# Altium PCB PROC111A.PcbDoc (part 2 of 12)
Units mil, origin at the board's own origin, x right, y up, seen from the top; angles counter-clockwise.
Board outline 7700 x 2300 mil, 6 copper layers (Top Layer, GND 1, SIG 1, SIG 2, GND 2, Bottom Layer), stack 61.062 mil thick; 841 components, 632 nets, 2914 pads, 1627 vias.
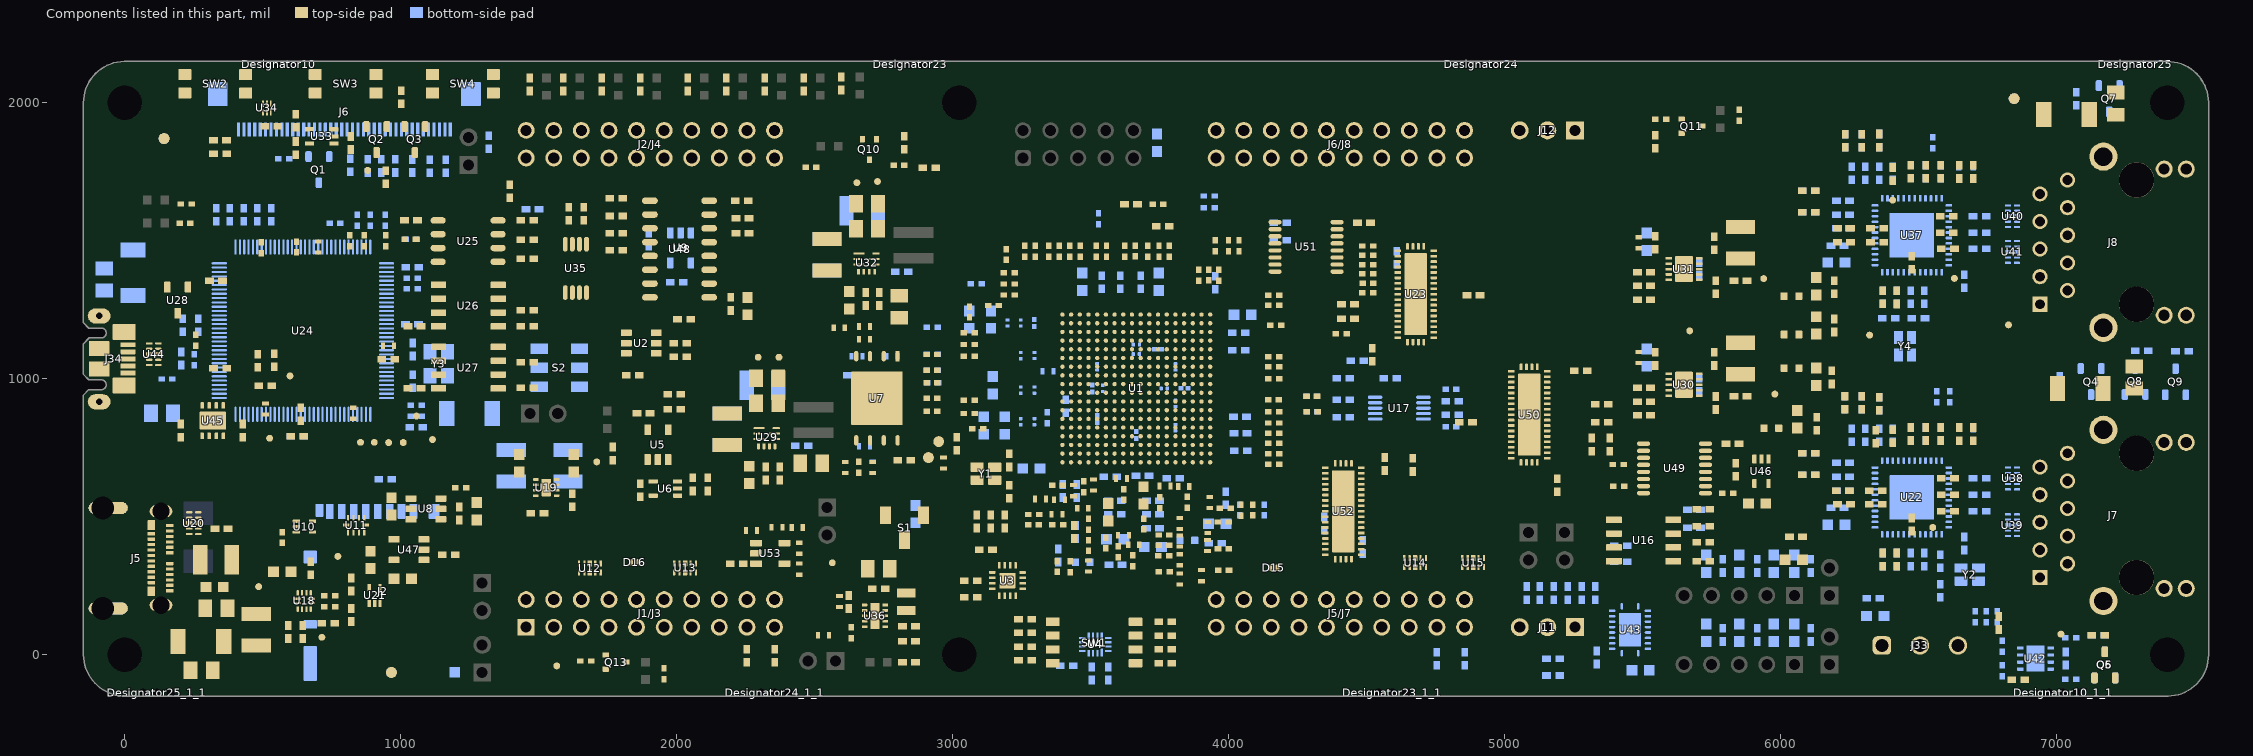
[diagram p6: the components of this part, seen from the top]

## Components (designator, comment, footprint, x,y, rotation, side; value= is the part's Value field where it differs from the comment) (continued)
Q3 "IRLML6401TRPBF" SOT-23 1051.12,1867.02 r270 top value=-12V
Q4 "BSS123" SOT-23 7124.1,990 r270 bottom value=100V
Q5 "BSS123" SOT-23 7174,-36.34 r90 top value=100V
Q6 "BSS123" SOT-23 7174,-36.34 r90 bottom value=100V
Q7 "BSS123" SOT-23 7190,2015 r270 bottom value=100V
Q8 "BSS123" SOT-23 7283.87,990.67 r90 bottom value=100V
Q9 "BSS123" SOT-23 7430.33,989.39 r90 bottom value=100V
Q10 "BSS223PWH6327" SOT-323 2698,1831 r270 top value=-20V
Q11 "BSS123W-7-F" SOT-323 5678,1915.27 r0 top value=100V
Q13 "BSS123W-7-F" SOT-323 1780,-26.61 r0 top value=100V
R1 "ERJ-2RKF1002X" 0402 3087.47,483.24 r270 top value=10.0k
R2 "CRCW04022K67FKED" 0402 3187.66,483.24 r90 top value=2.67k
R3 "ERJ-2GE0R00X" 0402L 3425.19,318.53 r90 top value=0
R4 "ERJ-2GE0R00X" 0402L 3090.9,819.06 r180 top value=0
R5 "ERJ-2GE0R00X" 0402 1898.11,1504.66 r270 bottom value=0
R6 "ERJ-2RKF1002X" 0402 2012.72,1079.13 r180 top value=10.0k
R7 "ERJ-2GE0R00X" 0402L 3260,1462.48 r90 top value=0
R8 "ERJ-2RKF1002X" 0402 3413.14,-40.23 r0 bottom value=10.0k
R9 "ERJ-2GE0R00X" 0402L 2924.77,1088.11 r0 top value=0
R10 "ERJ-2RKF1002X" 0402 3065,208.58 r0 top value=10.0k
R11 "ERJ-2RKF1002X" 0402 3120,380.76 r0 top value=10.0k
R12 "ERJ-2GE0R00X" 0402L 2924.77,985.05 r0 top value=0
R13 "ERJ-2GE0R00X" 0402L 2924.77,1031.64 r0 top value=0
R14 "ERJ-2RKF1002X" 0402 3261.93,-20.49 r0 top value=10.0k
R15 "ERJ-2RKF1002X" 0402 3261.93,29.51 r0 top value=10.0k
R16 "ERJ-2RKF1002X" 0402 3261.93,79.51 r0 top value=10.0k
R17 "ERJ-2RKF1002X" 0402 3261.93,129.51 r0 top value=10.0k
R18 "ERJ-2GE0R00X" 0402 1990.8,889.07 r0 top value=0
R19 "ERJ-2RKF49R9X" 0402 2112.84,617.39 r270 top value=49.9
R20 "ERJ-2RKF1002X" 0402 1990.8,944.07 r180 top value=10.0k
R21 "ERJ-2GEJ102X" 0402 1395,1679.63 r90 top value=1.0k
R22 "ERJ-2GEJ102X" 0402 3770,-30.49 r180 top value=1.0k
R23 "ERJ-2GEJ102X" 0402 3770,19.51 r180 top value=1.0k
R24 "ERJ-2GEJ102X" 0402 3770,69.51 r180 top value=1.0k
R25 "ERJ-2GEJ102X" 0402 3770,119.51 r180 top value=1.0k
R26 "ERJ-2GE0R00X" 0402L 2660,678.96 r270 top value=0
R27 "ERJ-2RKF33R0X" 0402S 2610,678.96 r270 top value=33.0
R28 "ERJ-2RKF33R0X" 0402S 2680,1189.27 r180 top value=33.0
R29 "ERJ-2RKF33R0X" 0402S 2680,1143.54 r180 top value=33.0
R30 "ERJ-2RKF33R0X" 0402S 2710,678.96 r270 top value=33.0
R31 "ERJ-2RKF1003X" 0402S 2680.31,755 r0 bottom value=100k
R32 "ERJ-6GEY0R00V" 0805_HV 278.45,-56.06 r0 top value=0
R33 "ERJ-2GE0R00X" 0402L 3519,1462.48 r90 top value=0
R34 "ERJ-2GE0R00X" 0402L 3423,1462.48 r90 top value=0
R35 "ERJ-2GE0R00X" 0402L 3461,1462.48 r90 top value=0
R36 "ERJ-2GE0R00X" 0402L 3385,1462.48 r90 top value=0
R37 "ERJ-2GE0R00X" 0402L 3347,1462.48 r90 top value=0
R38 "ERJ-2GE0R00X" 0402L 3299,1462.48 r90 top value=0
R39 "CRCW040210K0FKED" 0402L 1217.24,604.8 r180 top value=10.0k
R40 "CRCW040210K0FKED" 0402L 570.7,424.84 r270 top value=10.0k
R41 "CRCW040210K0FKED" 0402L 3528.01,1580 r90 bottom value=10.0k
R42 "ERJ-2RKF1002X" 0402 3014.53,764.8 r270 top value=10.0k
R43 "ERJ-2RKF1002X" 0402 2641.66,1013.59 r0 bottom value=10.0k
R44 "ERJ-2GE0R00X" 0402L 3691.48,473.8 r90 top value=0
R45 "ERJ-2GE0R00X" 0402L 3378.72,319.92 r90 top value=0
R46 "ERJ-2GE0R00X" 0402L 3194.16,1450.48 r270 top value=0
R47 "ERJ-2GE0R00X" 0402L 3205,1384 r0 top value=0
R48 "ERJ-2GE0R00X" 0402L 3084.69,1345 r0 bottom value=0
R49 "ERJ-2GE0R00X" 0402L 3147.5,1265.5 r0 top value=0
R50 "ERJ-2GE0R00X" 0402L 3205,1343.5 r0 top value=0
R51 "ERJ-2GE0R00X" 0402L 3205,1303.5 r0 top value=0
R52 "ERJ-2GE0R00X" 0402L 3060.5,1241.92 r270 top value=0
R53 "ERJ-2GE0R00X" 0402L 2925,1186.34 r0 bottom value=0
R54 "ERJ-2GE0R00X" 0402L 3059.68,1167.26 r0 top value=0
R55 "CRCW04024K70JNED" 0402 2254.17,-3.62 r270 top value=4.7k
R56 "CRCW04024K70JNED" 0402 2354.17,-3.62 r270 top value=4.7k
R57 "ERJ-2GE0R00X" 0402L 3059.68,1124.26 r0 top value=0
R58 "ERJ-2GE0R00X" 0402L 3059.68,1081.26 r0 top value=0
R59 "ERJ-2GE0R00X" 0402L 2925,1031.51 r0 bottom value=0
R60 "ERJ-2GE0R00X" 0402L 2927.77,985.05 r0 bottom value=0
R61 "ERJ-2RKF33R0X" 0402L 4805.28,825.79 r0 bottom value=33.0
R62 "ERJ-2RKF33R0X" 0402L 4805.28,961.7 r0 bottom value=33.0
R63 "CRCW04024K70JNED" 0402 4809.21,869.06 r0 bottom value=4.7k
R64 "CRCW04024K70JNED" 0402 4809.21,918.43 r0 bottom value=4.7k
R65 "ERJ-2GE0R00X" 0402L 4162.25,690.82 r180 top value=0
R66 "ERJ-2GE0R00X" 0402L 4162.25,728.82 r180 top value=0
R67 "ERJ-2GE0R00X" 0402L 4162.25,766.82 r180 top value=0
R68 "ERJ-2GE0R00X" 0402L 4162.25,802.82 r180 top value=0
R69 "ERJ-2GE0R00X" 0402L 4162.25,880.82 r180 top value=0
R70 "ERJ-2GE0R00X" 0402L 4162.25,839.82 r180 top value=0
R71 "ERJ-2RKF33R0X" 0402L 4162.05,923.63 r180 top value=33.0
R72 "ERJ-2RKF33R0X" 0402L 4301.61,936.73 r180 top value=33.0
R73 "CRCW04024K70JNED" 0402 4414.79,860.55 r180 bottom value=4.7k
R74 "CRCW04024K70JNED" 0402 4414.79,924.9 r180 bottom value=4.7k
R75 "ERJ-2GE0R00X" 0402L 4301.61,879.87 r180 bottom value=0
R76 "ERJ-2GE0R00X" 0402L 4302.24,879.87 r180 top value=0
R77 "ERJ-2GE0R00X" 0402L 4162.25,1044.35 r180 top value=0
R78 "ERJ-2GE0R00X" 0402L 4407.16,1163.21 r180 top value=0
R79 "ERJ-2GE0R00X" 0402L 4299.67,936.88 r180 bottom value=0
R80 "ERJ-2GE0R00X" 0402L 4162.25,999.75 r180 top value=0
R81 "ERJ-2GE0R00X" 0402L 4162.25,1302.77 r180 top value=0
R82 "ERJ-2GE0R00X" 0402L 4037,1482.48 r270 top value=0
R83 "ERJ-2GE0R00X" 0402L 4170.25,1194.45 r180 top value=0
R84 "ERJ-2GE0R00X" 0402L 4162.25,1265.85 r180 top value=0
R85 "ERJ-2GE0R00X" 0402L 3999,1482.48 r270 top value=0
R86 "ERJ-2GE0R00X" 0402L 3951,1482.48 r270 top value=0
R87 "ERJ-2GE0R00X" 0402L 3928.97,1619.24 r180 bottom value=0
R88 "ERJ-2GE0R00X" 0402L 3928.97,1662.24 r180 bottom value=0
R89 "ERJ-2GE0R00X" 0402L 742.82,174.31 r0 top value=0
R90 "ERJ-2GE0R00X" 0402L 742.82,214.41 r0 top value=0
R91 "CRCW0402200KJNED" 0402 737.51,113.69 r0 top value=200k
R92 "ERJ-2RKF1002X" 0402 819.95,254.69 r270 top value=10.0k
R93 "ERJ-2RKF1002X" 0402 819.95,144.31 r90 top value=10.0k
R94 "CRCW0402909KFKED" 0402 644.6,82.65 r270 top value=909k
R95 "CRCW04024K70JNED" 0402 591.65,82.48 r90 top value=4.7k
R96 "ERJ-2GEJ102X" 0402 5836.5,670 r270 top value=1.0k
R97 "ERJ-2GEJ102X" 0402 673.29,313.41 r270 top value=1.0k
R98 "ERJ-2RKF1002X" 0402 1495,513.27 r0 top value=10.0k
R99 "ERJ-2GE0R00X" 0402L 2924.77,929.62 r0 top value=0
R100 "ERJ-2GE0R00X" 0402 6225.51,595.04 r0 bottom value=0
R101 "ERJ-2GE0R00X" 0402 6356.28,795 r270 bottom value=0
R102 "ERJ-2GE0R00X" 0402 6225.51,645.04 r0 bottom value=0
R103 "ERJ-2GE0R00X" 0402 6225.51,695.04 r0 bottom value=0
R104 "ERJ-2GE0R00X" 0402 6256.28,795 r270 bottom value=0
R105 "ERJ-2GE0R00X" 0402 6306.28,795 r270 bottom value=0
R106 "ERJ-2GE0R00X" 0402 6343.31,790.44 r90 top value=0
R107 "ERJ-2RKF1152X" 0402 6665,403.37 r90 bottom value=11.5k
R108 "CRCW04022K49FKED" 0402 6101.3,652.65 r180 top value=2.49k
R109 "CRCW04022K49FKED" 0402 6101.38,730.96 r180 top value=2.49k
R110 "CRCW04022K49FKED" 0402 6579.39,800.08 r90 top value=2.49k
R111 "CRCW04022K49FKED" 0402 6646.28,799.68 r90 top value=2.49k
R112 "CRCW04022K49FKED" 0402 6524.39,800.08 r90 top value=2.49k
R113 "CRCW04022K49FKED" 0402 6356.28,909.68 r90 top value=2.49k
R114 "CRCW04022K49FKED" 0402 6370,345 r270 top value=2.49k
R115 "CRCW04022K49FKED" 0402 6233.01,912.96 r90 top value=2.49k
R116 "CRCW04022K49FKED" 0402 6293.01,912.97 r90 top value=2.49k
R117 "ERJ-2GE0R00X" 0402 6420,345 r90 bottom value=0
R118 "ERJ-2GE0R00X" 0402 6370,345 r90 bottom value=0
R119 "ERJ-2GE0R00X" 0402 6470,345 r90 bottom value=0
R120 "CRCW04022K49FKED" 0402 6101.3,652.65 r0 bottom value=2.49k
R121 "CRCW04022K49FKED" 0402 6101.49,730.85 r0 bottom value=2.49k
R122 "CRCW04022K49FKED" 0402 6579.39,800.08 r270 bottom value=2.49k
R123 "CRCW04022K49FKED" 0402 6698,799.68 r270 top value=2.49k
R124 "CRCW04022K49FKED" 0402 6524.39,800.08 r270 bottom value=2.49k
R125 "CRCW04022K49FKED" 0402 6356.28,909.68 r270 bottom value=2.49k
R126 "CRCW04022K49FKED" 0402 6420.85,345 r90 top value=2.49k
R127 "CRCW04022K49FKED" 0402 6229.14,912.97 r270 bottom value=2.49k
R128 "CRCW04022K49FKED" 0402 6293.01,912.97 r270 bottom value=2.49k
R129 "ERJ-2GE0R00X" 0402 330.5,1594.01 r270 bottom value=0
R130 "ERJ-2GE0R00X" 0402L 1055.5,904.21 r180 bottom value=0
R131 "ERJ-2GE0R00X" 0402 380.5,1594.01 r270 bottom value=0
R132 "ERJ-2GEJ101X" 0402L 1055.5,864.22 r0 bottom value=100
R133 "CRCW040233R2FKED" 0402 430.5,1594.01 r270 bottom value=33.2
R134 "CRCW040233R2FKED" 0402 480.5,1594.01 r270 bottom value=33.2
R135 "CRCW040233R2FKED" 0402 530.5,1594.01 r270 bottom value=33.2
R136 "CRCW0402330KFKED" 0402L 152.83,999.2 r180 bottom value=330k
R137 "CRCW0402330KFKED" 0402L 251.47,1069.49 r270 bottom value=330k
R138 "CRCW04021K00FKED" 0402L 1037.62,1506.39 r0 bottom value=1.00k
R139 "CRCW04021K00FKED" 0402L 943.35,1574.68 r90 bottom value=1.00k
R140 "CRCW04021K00FKED" 0402L 889.13,1574.68 r90 bottom value=1.00k
R141 "CRCW04021K00FKED" 0402L 842.24,1574.68 r90 bottom value=1.00k
R142 "CRCW040249R9FKED" 0402L 1041.36,1364.93 r0 bottom value=49.9
R143 "CRCW040210K0FKED" 0402L 1041.36,1326.93 r0 bottom value=10.0k
R144 "CRCW04021K00FKED" 0402L 257.13,1139.87 r270 top value=1.00k
R145 "CRCW04024K87FKED" 0402L 761.79,1563.62 r0 bottom value=4.87k
R146 "ERJ-2RKF1002X" 0402 2452.33,756.68 r0 bottom value=10.0k
R147 "ERJ-2RKF1002X" 0402 5504.13,967.63 r180 top value=10.0k
R148 "ERJ-6ENF1822V" 0805_HV 2487.33,694.68 r180 top value=18.2k
R149 "ERJ-2GE0R00X" 0402 5504.13,867.63 r0 top value=0
R150 "ERJ-2GE0R00X" 0402 5504.13,917.63 r0 top value=0
R151 "CRCW04023K57FKED" 0402 5854.13,935.98 r0 top value=3.57k
R152 "CRCW04021K69FKED" 0402 5764.13,912.36 r90 top value=1.69k
R153 "CRCW04022K49FKED" 0402 2372.33,656.68 r270 top value=2.49k
R154 "CRCW04024K99FKED" 0402 2322.33,656.68 r90 top value=4.99k
R155 "ERJ-2RKF1002X" 0402 5504.13,1386.82 r180 top value=10.0k
R156 "ERJ-2RKF1002X" 0402 2815.12,1387.88 r0 bottom value=10.0k
R157 "ERJ-2GE0R00X" 0402 5504.13,1286.82 r0 top value=0
R158 "ERJ-2GE0R00X" 0402 5504.13,1336.82 r0 top value=0
R159 "CRCW04021K87FKED" 0402 5854.13,1355.17 r0 top value=1.87k
R160 "ERJ-6ENF1822V" 0805_HV 2806.47,1260.85 r90 top value=18.2k
R161 "CRCW04024K99FKED" 0402 5764.13,1331.55 r90 top value=4.99k
R162 "CRCW040215K4FKED" 0402 2734,1289.3 r270 top value=15.4k
R163 "CRCW04024K99FKED" 0402 2684,1289.3 r90 top value=4.99k
R164 "ERJ-2GE0R00X" 0402L 3557,1462.48 r270 top value=0
R165 "ERJ-2GE0R00X" 0402L 3342.19,859.41 r90 bottom value=0
R166 "ERJ-2GE0R00X" 0402L 3623,1462.48 r270 top value=0
R167 "ERJ-2GE0R00X" 0402L 3059.68,874.38 r0 top value=0
R168 "ERJ-2GE0R00X" 0402L 3059.68,922.38 r0 top value=0
R169 "ERJ-2GE0R00X" 0402L 3785,1462.48 r270 top value=0
R170 "ERJ-2GE0R00X" 0402L 3743.31,1631.65 r0 top value=0
R171 "ERJ-2GE0R00X" 0402L 3747,1462.48 r270 top value=0
R172 "ERJ-2GE0R00X" 0402L 3707,1462.48 r270 top value=0
R173 "ERJ-2RKF1002X" 0402 3760.59,1552.62 r180 top value=10.0k
R174 "ERJ-2RKF1002X" 0402 3645.44,1631.65 r180 top value=10.0k
R175 "CRCW04024K70JNED" 0402 4753.31,-13.97 r270 bottom value=4.7k
R176 "CRCW04024K70JNED" 0402 4854.17,-13.97 r270 bottom value=4.7k
R177 "ERJ-2RKF1002X" 0402 816.87,1773.62 r270 bottom value=10.0k
R178 "ERJ-2RKF1002X" 0402 818.08,1854.52 r270 top value=10.0k
R179 "ERJ-2RKF1002X" 0402 619.09,1935.36 r90 top value=10.0k
R180 "ERJ-2GE0R00X" 0402L 575.69,1797.32 r180 bottom value=0
R181 "ERJ-2RKF1002X" 0402 1001.5,2020 r90 top value=10.0k
R182 "ERJ-2RKF1002X" 0402 1105,1770 r90 bottom value=10.0k
R183 "ERJ-2RKF1002X" 0402 1477.39,1615 r180 bottom value=10.0k
R184 "ERJ-2RKF1002X" 0402 944.86,1730 r90 top value=10.0k
R185 "ERJ-2RKF1002X" 0402 1040.9,1770.91 r90 bottom value=10.0k
R186 "ERJ-2RKF1002X" 0402 979.84,1771.38 r90 bottom value=10.0k
R187 "ERJ-2RKF1002X" 0402 929.84,1771.38 r90 bottom value=10.0k
R188 "ERJ-2RKF1002X" 0402 879.84,1771.38 r90 bottom value=10.0k
R189 "CRCW04024K70JNED" 0402 1318,1857 r90 bottom value=4.7k
R190 "CRCW04024K70JNED" 0402 1663.28,1598.34 r90 top value=4.7k
R191 "CRCW04024K70JNED" 0402 1162.52,1770 r270 bottom value=4.7k
R192 "CRCW04024K70JNED" 0402 1608.28,1598.34 r90 top value=4.7k
R193 "ERJ-2GE0R00X" 0402L 2631.5,80.04 r270 top value=0
R194 "ERJ-2RKF1002X" 0402 2841.5,103.66 r0 top value=10.0k
R195 "ERJ-2RKF1003X" 0402 2841.5,48.66 r0 top value=100k
R196 "ERJ-2GE0R00X" 0402 6225.51,1545.04 r0 bottom value=0
R197 "ERJ-2GE0R00X" 0402 6356.28,1745 r270 bottom value=0
R198 "ERJ-2GE0R00X" 0402 6225.51,1595.04 r0 bottom value=0
R199 "ERJ-2GE0R00X" 0402 6225.51,1645.04 r0 bottom value=0
R200 "ERJ-2GE0R00X" 0402 6256.28,1745 r270 bottom value=0
R201 "ERJ-2GE0R00X" 0402 6306.28,1745 r270 bottom value=0
R202 "ERJ-2RKF1152X" 0402 6665,1353.37 r90 bottom value=11.5k
R203 "CRCW04022K49FKED" 0402 6101.38,1602.65 r180 top value=2.49k
R204 "CRCW04022K49FKED" 0402 6101.38,1680.96 r180 top value=2.49k
R205 "CRCW04022K49FKED" 0402 6356.28,1863.05 r90 top value=2.49k
R206 "CRCW04022K49FKED" 0402 6646.28,1749.68 r90 top value=2.49k
R207 "CRCW04022K49FKED" 0402 6524.39,1750.08 r90 top value=2.49k
R208 "CRCW04022K49FKED" 0402 6579.39,1750.08 r90 top value=2.49k
R209 "CRCW04022K49FKED" 0402 6370,1295 r270 top value=2.49k
R210 "CRCW04022K49FKED" 0402 6233.01,1862.97 r90 top value=2.49k
R211 "CRCW04022K49FKED" 0402 6293.01,1862.97 r90 top value=2.49k
R212 "ERJ-2GE0R00X" 0402 6420,1295 r90 bottom value=0
R213 "ERJ-2GE0R00X" 0402 6370,1295 r90 bottom value=0
R214 "ERJ-2GE0R00X" 0402 6470,1295 r90 bottom value=0
R215 "CRCW04022K49FKED" 0402 6101.3,1602.65 r0 bottom value=2.49k
R216 "CRCW04022K49FKED" 0402 6101.38,1680.96 r0 bottom value=2.49k
R217 "CRCW04022K49FKED" 0402 6356.28,1863.05 r270 bottom value=2.49k
R218 "CRCW04022K49FKED" 0402 6698,1749.68 r270 top value=2.49k
R219 "CRCW04022K49FKED" 0402 6524.39,1750.08 r270 bottom value=2.49k
R220 "CRCW04022K49FKED" 0402 6579.39,1750.08 r270 bottom value=2.49k
R221 "CRCW04022K49FKED" 0402 6420.97,1294.88 r90 top value=2.49k
R222 "CRCW04022K49FKED" 0402 6233.01,1862.97 r270 bottom value=2.49k
R223 "CRCW04022K49FKED" 0402 6293.01,1862.97 r270 bottom value=2.49k
R224 "CRCW0402220RJNED" 0402 7010.2,985 r270 bottom value=220
R225 "ERJ-2GE0R00X" 0402L 6565,934.62 r270 bottom value=0
R226 "CRCW0402220RJNED" 0402 7150.38,71.46 r180 top value=220
R227 "ERJ-2GE0R00X" 0402L 6612.73,935 r270 bottom value=0
R228 "CRCW0402220RJNED" 0402 7150.38,71.46 r180 bottom value=220
R229 "ERJ-2GE0R00X" 0402L 6696.59,797.67 r270 bottom value=0
R230 "CRCW0402220RJNED" 0402 7070,2015 r270 bottom value=220
R231 "ERJ-2GE0R00X" 0402L 6550,1854.69 r270 bottom value=0
R232 "CRCW0402220RJNED" 0402 7307.49,1101.28 r0 bottom value=220
R233 "ERJ-2GE0R00X" 0402L 6645,1746.38 r270 bottom value=0
R234 "CRCW0402220RJNED" 0402 7453.95,1100 r0 bottom value=220
R235 "ERJ-2GE0R00X" 0402L 6698,1746.38 r270 bottom value=0
R236 "ERJ-2RKF4992X" 0402 6109.18,72.12 r90 bottom value=49.9k
R237 "ERJ-2RKF4992X" 0402 5914.18,72.13 r90 bottom value=49.9k
R238 "ERJ-2RKF4992X" 0402 5790,72.13 r90 bottom value=49.9k
R239 "ERJ-2RKF4992X" 0402 6109.18,322.12 r90 bottom value=49.9k
R240 "ERJ-2RKF4992X" 0402 5914.18,322.13 r90 bottom value=49.9k
R241 "ERJ-2RKF4992X" 0402 5790,322.13 r90 bottom value=49.9k
R242 "ERJ-2RKF4992X" 0402 6335.13,205.53 r0 bottom value=49.9k
R243 "ERJ-2RKF4992X" 0402 6055,428.2 r180 top value=49.9k
R244 "CRCW040210K0FKED" 0402L 6785,137.55 r90 bottom value=10.0k
R245 "ERJ-2GE0R00X" 0402L 7050,61.46 r180 bottom value=0
R246 "CRCW040261R9FKED" 0402L 6802.8,-58.23 r90 bottom value=61.9
R247 "CRCW040261R9FKED" 0402L 6802.8,31.14 r270 bottom value=61.9
R248 "ERJ-2GE0R00X" 0402L 6705,137.55 r90 bottom value=0
R249 "ERJ-2GE0R00X" 0402L 7050,-88.54 r180 bottom value=0
R250 "CRCW040210K0FKED" 0402L 6745,137.55 r270 bottom value=10.0k
R251 "CRCW040251K1FKED" 0402 481.97,1065.23 r90 top value=51.1k
R252 "CRCW040230K0FKED" 0402 541.97,1067.17 r270 top value=30.0k
R253 "ERJ-6GEY0R00V" 0805_HV -74.82,1359.48 r90 bottom value=0
R254 "ERJ-6ENF1004V" 0805_HV 7280.57,1005 r90 top value=1.00Meg
R255 "ERJ-6ENF1004V" 0805_HV 7214.16,1996.97 r90 top value=1.00Meg
R256 "ERJ-2GEJ102X" 0402 4666.77,688.02 r90 top value=1.0k
R257 "ERJ-2RKF5100X" 0402 1768.27,729.01 r270 top value=510
R258 "ERJ-2RKF1002X" 0402 2824.53,1855.57 r90 top value=10.0k
R259 "ERJ-2GEJ361X" 0402L 218.02,1563.38 r0 top value=360
R260 "ERJ-2GEJ361X" 0402L 223.02,1633.38 r0 top value=360
R261 "CRCW04021K00FKED" 0402L 815,1500 r270 top value=1.00k
R262 "ERJ-2RKF2200X" 0402 2459.29,2066.18 r270 top value=220
R263 "ERJ-2RKF2200X" 0402 2319.29,2066.18 r270 top value=220
R264 "ERJ-2RKF2200X" 0402 2179.29,2066.18 r270 top value=220
R265 "ERJ-2GEJ361X" 0402L 2486.09,1767.12 r180 top value=360
R266 "ERJ-2RKF2200X" 0402 2039.29,2066.18 r270 top value=220
R267 "ERJ-2RKF2200X" 0402 1867.87,2066.18 r270 top value=220
R268 "ERJ-2RKF1002X" 0402 2915,1765.46 r0 top value=10.0k
R269 "ERJ-2RKF1002X" 0402 2238.01,1581.55 r180 top value=10.0k
R270 "ERJ-2RKF1002X" 0402 1780.93,1526.88 r0 top value=10.0k
R271 "ERJ-2RKF1002X" 0402 1780.93,1654.54 r0 top value=10.0k
R272 "ERJ-2GEJ511X" 0402L 2805,1773.35 r180 top value=510
R273 "ERJ-2RKF2200X" 0402 1727.87,2066.18 r270 top value=220
R274 "ERJ-2RKF1002X" 0402 1780.93,1589.85 r0 top value=10.0k
R275 "ERJ-2RKF1002X" 0402 2238.01,1526.55 r180 top value=10.0k
R276 "ERJ-2RKF1002X" 0402 1780.93,1466.57 r0 top value=10.0k
R277 "ERJ-2RKF2200X" 0402 1587.87,2066.18 r270 top value=220
R278 "ERJ-2GEJ102X" 0402 2235,1645 r180 top value=1.0k
R279 "ERJ-2RKF2200X" 0402 1467.87,2066.18 r270 top value=220
R280 "ERJ-2GE0R00X" 0402L 2924.77,881.94 r0 top value=0
R281 "ERJ-2GE0R00X" 0402L 2925,1089.6 r0 bottom value=0
R282 "ERJ-2GE0R00X" 0402L 4044.18,523.45 r90 top value=0
R283 "ERJ-2GE0R00X" 0402L 4040,524.68 r90 bottom value=0
R284 "ERJ-2GE0R00X" 0402L 4127.93,524.68 r90 bottom value=0
R285 "ERJ-2GE0R00X" 0402L 4086.47,524.68 r90 top value=0
R286 "ERJ-2GE0R00X" 0402L 4162.25,1080 r180 top value=0
R287 "ERJ-2RKF1002X" 0402 5380,761.55 r90 top value=10.0k
R288 "ERJ-2RKF1002X" 0402 4431.73,1270.9 r0 top value=10.0k
R289 "ERJ-2GEJ102X" 0402 5315.31,761.55 r90 top value=1.0k
R290 "ERJ-2GEJ102X" 0402 4431.73,1217.93 r0 top value=1.0k
R291 "ERJ-2RKF1002X" 0402 4415,1002.36 r0 bottom value=10.0k
R292 "ERJ-2RKF1002X" 0402 5351.38,907.02 r180 top value=10.0k
R293 "ERJ-2GEJ102X" 0402 4465.26,1065.33 r180 bottom value=1.0k
R294 "ERJ-2GEJ102X" 0402 5351.38,842.02 r180 top value=1.0k
R295 "ERJ-2RKF1002X" 0402 1840,1013.59 r0 top value=10.0k
R296 "ERJ-2RKF1002X" 0402 2026.41,1215 r0 top value=10.0k
R297 "ERJ-2GE0R00X" 0402L 3661,1462.92 r270 top value=0
R298 "ERJ-2RKF1002X" 0402 4186.51,1565.49 r180 bottom value=10.0k
R299 "ERJ-2RKF1002X" 0402 1173.5,362.5 r0 top value=10.0k
R300 "ERJ-2GEJ102X" 0402 4186.51,1502.52 r180 bottom value=1.0k
R301 "ERJ-2RKF1003X" 0402S 2966.47,694.56 r270 top value=100k
R302 "ERJ-2GEJ361X" 0402L 5850,1954.27 r270 top value=360
R303 "ERJ-2GEJ511X" 0402L 5565,1940.86 r0 top value=510
R304 "ERJ-2GEJ102X" 0402 5545.31,1858.64 r90 top value=1.0k
R305 "ERJ-2RKF1002X" 0402 6470,800 r270 top value=10.0k
R306 "ERJ-2RKF1002X" 0402 6470,1750.08 r270 top value=10.0k
R307 "ERJ-2GE0R00X" 0402L 3553.62,405 r90 top value=0
R308 "CRCW04021K00FKED" 0402L 866.99,1500 r270 top value=1.00k
R309 "CRCW04021K00FKED" 0402L 945.89,1500 r270 top value=1.00k
R310 "CRCW04021K00FKED" 0402L 1034.6,1506.39 r0 top value=1.00k
R311 "CRCW04021K00FKED" 0402L 495,1475 r270 top value=1.00k
R312 "CRCW04021K00FKED" 0402L 622.07,1477.63 r270 top value=1.00k
R313 "CRCW0402130RFKED" 0402 2595.47,2070.12 r270 top value=130
R314 "ERJ-2GEJ361X" 0402L 1953.52,-68.1 r90 top value=360
R315 "CRCW0402130RFKED" 0402 2841.5,-26.59 r0 top value=130
R316 "ERJ-2RKF1002X" 0402 5420,395.04 r0 bottom value=10.0k
R317 "ERJ-2GEJ511X" 0402L 1669.99,-22.51 r0 top value=510
R318 "ERJ-2RKF1002X" 0402 5718.93,338.21 r180 top value=10.0k
R319 "ERJ-2RKF1002X" 0402 5685.31,525 r180 bottom value=10.0k
R320 "ERJ-2RKF1002X" 0402 5718.93,526.73 r180 top value=10.0k
R321 "ERJ-2RKF1002X" 0402 5718.93,406.99 r180 top value=10.0k
R322 "ERJ-2RKF1002X" 0402 5685.31,461.02 r180 bottom value=10.0k
R323 "ERJ-2RKF1002X" 0402 5718.93,465 r180 top value=10.0k
R324 "CRCW040233R2FKED" 0402 1457.87,1503.35 r180 top value=33.2
R325 "CRCW040233R2FKED" 0402 1457.87,1434.92 r180 top value=33.2
R326 "CRCW040233R2FKED" 0402 1457.87,1248.01 r180 top value=33.2
R327 "CRCW040233R2FKED" 0402 1457.87,1060 r180 top value=33.2
R328 "CRCW040233R2FKED" 0402 5175,-75 r0 bottom value=33.2
R329 "CRCW040233R2FKED" 0402 5175,-14.91 r0 bottom value=33.2
R330 "CRCW040233R2FKED" 0402 5079.44,223.51 r270 bottom value=33.2
R331 "CRCW040233R2FKED" 0402 5127.45,223.51 r270 bottom value=33.2
R332 "CRCW040233R2FKED" 0402 5177.45,223.51 r270 bottom value=33.2
R333 "CRCW040233R2FKED" 0402 5227.45,223.51 r270 bottom value=33.2
R334 "CRCW040233R2FKED" 0402 5278.06,223.51 r270 bottom value=33.2
R335 "CRCW040233R2FKED" 0402 5328.01,223.51 r270 bottom value=33.2
R336 "ERJ-2RKF1003X" 0402S 2588.43,1184.92 r180 top value=100k
R337 "ERJ-2RKF1003X" 0402S 2779.53,1082.25 r180 bottom value=100k
R338 "CRCW040210K0FKED" 0402S 2653.04,1082.25 r0 bottom value=10.0k
R339 "CRCW040210K0FKED" 0402S 2710,679.28 r90 bottom value=10.0k
R340 "ERJ-2GE0R00X" 0402L 3979.84,481.1 r180 top value=0
R341 "ERJ-2GE0R00X" 0402L 3986.76,531.48 r180 top value=0
R342 "ERJ-2GE0R00X" 0402L 3765.21,396.86 r0 top value=0
R343 "ERJ-2GE0R00X" 0402L 3980.55,384.81 r180 top value=0
R344 "ERJ-2GE0R00X" 0402L 3763.9,358.71 r0 top value=0
R345 "ERJ-2GE0R00X" 0402L 3749.25,550.87 r90 top value=0
R346 "ERJ-2GE0R00X" 0402L 3765.21,434.08 r0 top value=0
R347 "ERJ-2GE0R00X" 0402L 3849.44,552.1 r90 top value=0
R348 "ERJ-2GE0R00X" 0402L 3981.03,306.81 r180 top value=0
R349 "ERJ-2GE0R00X" 0402L 3765.9,301.47 r0 top value=0
R350 "ERJ-2GE0R00X" 0402L 3651.61,341.07 r90 top value=0
R351 "ERJ-2GE0R00X" 0402L 3599.24,373.81 r90 top value=0
R352 "ERJ-2GE0R00X" 0402L 3292.91,508.24 r0 top value=0
R353 "ERJ-2GE0R00X" 0402L 3620.06,580.66 r90 top value=0
R354 "ERJ-2GE0R00X" 0402L 3292.48,471.26 r0 top value=0
R355 "ERJ-2GE0R00X" 0402L 3379.18,614.48 r0 top value=0
R356 "ERJ-2GE0R00X" 0402L 3491.62,472.56 r90 top value=0
R357 "ERJ-2GE0R00X" 0402L 3474.28,608.47 r90 top value=0
R358 "ERJ-2GE0R00X" 0402L 3491.62,396.04 r270 top value=0
R359 "ERJ-2GE0R00X" 0402L 3379.96,471.26 r180 top value=0
R360 "ERJ-2GE0R00X" 0402L 4503.6,1481.27 r180 top value=0
R361 "ERJ-2GE0R00X" 0402L 4503.6,1447.48 r180 top value=0
R362 "ERJ-2GE0R00X" 0402L 4503.53,1413.86 r180 top value=0
R363 "ERJ-2GE0R00X" 0402L 4502.93,1380.23 r180 top value=0
R364 "ERJ-2GE0R00X" 0402L 4504.29,1346.57 r180 top value=0
R365 "ERJ-2GE0R00X" 0402L 5410.43,689.41 r180 top value=0
R366 "ERJ-2GE0R00X" 0402L 4503.09,1312.1 r180 top value=0
R367 "ERJ-2GE0R00X" 0402L 5413.34,611.25 r180 top value=0
R368 "ERJ-2GE0R00X" 0402L 5808.24,585.59 r0 top value=0
R369 "ERJ-2RKF33R0X" 0402L 3963.34,1375.6 r270 top value=33.0
R370 "ERJ-2RKF33R0X" 0402L 3927.56,1376.03 r270 top value=33.0
R371 "ERJ-2RKF33R0X" 0402L 3890.45,1375.36 r270 top value=33.0
R372 "CRCW040210K5FKED" 0402S 2444.32,385.99 r90 top value=10.5k
R373 "CRCW04024K99FKED" 0402S 2444.32,310.17 r90 top value=4.99k
R374 "ERJ-2RKF1002X" 0402S 2531.35,71.19 r180 top value=10.0k
R375 "ERJ-2RKF1003X" 0402 2217.34,330.17 r0 top value=100k
R376 "ERJ-2GE0R00X" 0402S 2436.29,461.13 r180 top value=0
R377 "ERJ-2RKF1002X" 0402 350.19,457.26 r180 top value=10.0k
S1 "CAS-120TA" SW_CAS-120TA 2825.61,460.94 r270 top
S2 "CAS-D20TA" SW_CAS-D20TA 1574.71,1040 r180 bottom
SH-J1 "60900213421" Wurth_60900213421 12835,2525 r90 top
SH-J2 "60900213421" Wurth_60900213421 9440,2358.18 r90 top
SH-J3 "60900213421" Wurth_60900213421 9440,1996.97 r90 top
SH-J4 "60900213421" Wurth_60900213421 1700.31,-430 r180 top
SH-J5 "60900213421" Wurth_60900213421 1725,-310 r180 top
SH-J6 "60900213421" Wurth_60900213421 4205,-270 r180 top
SH-J7 "60900213421" Wurth_60900213421 4195,-400 r180 top
SH-J8 "60900213421" Wurth_60900213421 7658,1366 r90 top
SW1 "416131160804" FP-416131160804_SMT_SW-MFG 3512.3,44.51 r90 top
SW2 "434351045816" FP-434351045816_SMT_SW_4MM7_4MM5-MFG 327.56,2068.82 r180 top
SW3 "434351045816" FP-434351045816_SMT_SW_4MM7_4MM5-MFG 800,2068.82 r180 top
SW4 "434351045816" FP-434351045816_SMT_SW_4MM7_4MM5-MFG 1225,2068.82 r180 top
TP1 "TP_SM_1MM" TP_SM_1MM 2948.87,772.75 r90 top
TP2 "TP_SM_1MM" TP_SM_1MM 2911.79,714.43 r90 top
TP3 "TESTPOINT" TP_25MIL-SMT 771.9,356.67 r90 top
TP4 "TESTPOINT" TP_25MIL-SMT 485.03,247.07 r180 top
TP5 "TESTPOINT" TP_25MIL-SMT 714.09,63.5 r90 top
TP6 "TESTPOINT" TP_25MIL-SMT 2563.35,333.41 r90 top
TP7 "TESTPOINT" TP_25MIL-SMT 6550.57,461.5 r180 top
TP8 "TESTPOINT" TP_25MIL-SMT 1710,698.96 r90 top
TP9 "TESTPOINT" TP_25MIL-SMT 2727.25,1715 r90 top
TP10 "TESTPOINT" TP_25MIL-SMT 2370,1078.07 r90 top
TP11 "TESTPOINT" TP_25MIL-SMT 5938.14,1363.04 r90 top
TP12 "TESTPOINT" TP_25MIL-SMT 5978.41,944.72 r90 top
TP13 "TESTPOINT" TP_25MIL-SMT 1565,-40 r90 top
TP14 "TESTPOINT" TP_25MIL-SMT 2652.41,1710.51 r90 top
TP15 "TESTPOINT" TP_25MIL-SMT 2295,1078.07 r90 top
TP16 "TESTPOINT" TP_25MIL-SMT 6321.65,1158.13 r90 top
TP17 "TESTPOINT" TP_25MIL-SMT 5670,1173.71 r90 top
TP18 "TESTPOINT" TP_25MIL-SMT 880,1755 r90 top
TP19 "TESTPOINT" TP_25MIL-SMT 6629.03,1363.91 r0 top
TP20 "TESTPOINT" TP_25MIL-SMT 6405,1647.09 r270 top
TP21 "TESTPOINT" TP_25MIL-SMT 6825,1195.45 r90 top
TP22 "TESTPOINT" TP_25MIL-SMT 7015,75 r90 top
TP23 "TESTPOINT" TP_25MIL-SMT 1057.03,865 r90 top
TP24 "TESTPOINT" TP_25MIL-SMT 598.48,1010.35 r0 top
TP25 "TESTPOINT" TP_25MIL-SMT 524.75,784.53 r270 top
TP26 "TESTPOINT" TP_25MIL-SMT 1115,779.89 r0 top
TP27 "TESTPOINT" TP_25MIL-SMT 853.9,770 r270 top
TP28 "TESTPOINT" TP_25MIL-SMT 903.9,770 r270 top
TP29 "TESTPOINT" TP_25MIL-SMT 955.9,769 r270 top
TP30 "TESTPOINT" TP_25MIL-SMT 1008.9,769 r270 top
U1 "AM2634COMFHAZCZR" "ZCZ (S-PBGA-N324)" 3397.13,1232.8 r0 top locked
U2 "SN74LVC1G11DBVR" DBV0006A_N 1871.24,1129.45 r0 top
U3 "TCA6408ARGTR" RGT0016A 3198.05,268.7 r90 top
U4 "SN74AVC4T245RSVR" RSV0016A 3516.07,37.78 r90 bottom
U5 "SN74LVC1G08DBVR" DBV0005A_N 1931.31,761.4 r90 top
U6 "SN74LVC1G17DCKR" DCK0005A_N 1958.67,602.39 r180 top
U7 "S25FL128SAGNFI000" FP-S25FL128SAGNFI000_WSON8-IPC_B 2725,929.5 r270 top locked
U8 "TPS22918TDBVTQ1" DBV0006A_N 1091.03,528.6 r180 top
U9 "SN74LVC1G08DBVR" DBV0005A_N 2013.97,1474.3 r270 bottom
U10 "TPD2E001DRLR" DRL0005A 650.76,464.21 r0 top
U11 "TPD6E001RSER" RSE0010A 838.2,470 r270 top
U12 "TPD4E02B04DQAR" DQA0010A#1 1685,314.48 r90 top
U13 "TPD4E02B04DQAR" DQA0010A#1 2030,315 r90 top
U14 "TPD4E02B04DQAR" DQA0010A#1 4675,334.12 r90 top
U15 "TPD4E02B04DQAR" DQA0010A#1 4885.4,334.26 r90 top
U16 "CAT24M01WI-GT3" SOIC-8 5502.8,414.14 r180 top
U17 "TS5A23159DGSR" DGS0010A_N 4617.68,893.75 r0 bottom
U18 "TUSB320LIRWBR" RWB0012A 650.2,195.09 r0 top
U19 "TPS22965TDSGRQ1" DSG0008B 1526.92,605.91 r0 top
U20 "TPD4E02B04DQAR" DQA0010A#1 249.85,476.95 r0 top
U21 "SN74AHC1G02DRLR" DRL0005A 905.3,215 r90 top
U22 "DP83869HMRGZT" RGZ0048B-MFG 6475.18,570.04 r180 bottom
U23 "TS3DDR3812RUAR" RUA0042A-MFG 4677.2,1306.5 r0 top
U24 "TM4C1294NCPDTT3" PDT0128A 645.5,1174.37 r0 bottom locked
U25 "ISO7220CDR" D0008B_N 1243.86,1498.86 r0 top
U26 "ISO7721DR" D0008B_HV 1245,1265 r180 top
U27 "ISO7721DR" D0008B_HV 1245,1040.27 r180 top
U28 "LM4040C25QDBZR" DBZ0003A_N 191.5,1284.76 r270 top
U29 "TPS62913RPUR" RPU0010A-MFG 2325.89,791.68 r180 top
U30 "TPS74801DRCR" DRC0010J 5649.13,978.43 r0 top
U31 "TPS74801DRCR" DRC0010J 5649.13,1397.62 r0 top
U32 "TPS62913RPUR" RPU0010A-MFG 2687.56,1424.3 r180 top
U33 "SN74LVC1G07DCKT" DCK0005A_N 713.37,1878.15 r180 top
U34 "SN74LVC2G17DSF2" DSF0006A 515,1981.22 r270 top
U35 "TCA9617BDGKR" DGK0008A_N 1634.37,1400 r90 top
U36 "TPS62177DQCR" DQC0010A 2717.72,141.06 r0 top
U37 "DP83869HMRGZT" RGZ0048B-MFG 6475.18,1520.04 r180 bottom
U38 "TPD4E05U06DQAR" DQA0010A#2 6839.58,638.94 r180 bottom
U39 "TPD4E05U06DQAR" DQA0010A#2 6839.31,469.6 r180 bottom
U40 "TPD4E05U06DQAR" DQA0010A#2 6839.58,1588.94 r180 bottom
U41 "TPD4E05U06DQAR" DQA0010A#2 6839.31,1459.6 r180 bottom
U42 "TCAN1044VDRBTQ1" DRB0008J 6922.8,-13.54 r180 bottom
U43 "TXB0108RGYR" RGY0020A 5453.66,90.62 r0 bottom
U44 "TPD4E02B04DQAR" DQA0010A#1 105,1088.92 r180 top
U45 "TPS79601DRBR" DRB0008B 318.69,848.32 r90 top
U46 "SN74LVC1G04DCKR" DCK0005A_N 5930,665 r270 top
U47 "SN74LVC1G08DBVR" DBV0005A_N 1029.5,381 r180 top
U48 "TPIC2810D" D0016A_N 2010,1470 r180 top locked
U49 "SN74CB3Q3257PWR" PW0016A_L 5615,675.23 r0 top
U50 "TS3DDR3812RUAR" RUA0042A-MFG 5088.39,870.04 r180 top
U51 "SN74CB3Q3257PWR" PW0016A_L 4280,1477.91 r0 top
U52 "TS3DDR3812RUAR" RUA0042A-MFG 4415,520 r180 top
U53 "TLV75801PDBVT" DBV0005A-MFG 2338.62,367.57 r0 top
Y1 "ABM10W-25.0000MHZ-4-D1X-T3" Abracon_ABM10W 3120,656.21 r90 top
Y2 "ABM10W-25.0000MHZ-4-D1X-T3" Abracon_ABM10W 6684.6,290.5 r90 bottom
Y3 "NX3225GA-16.000M-STD-CRG-1" NDK_NX3225GA 1137.13,1054.32 r180 bottom
Y4 "ABM10W-25.0000MHZ-4-D1X-T3" Abracon_ABM10W 6450,1118.41 r0 bottom
ZZ1 "This Assembly Note is for PCB labels only" AssemblyNoteLabel -10,5510 r0 top
ZZ2 "These assemblies are ESD sensitive, ESD precautions shall be observed." AssemblyNote -10,5410 r0 top
ZZ3 "These assemblies must be clean and free from flux and all contaminants. Use of no clean flux is not acceptable." AssemblyNote -10,5310 r0 top
ZZ4 "These assemblies must comply with workmanship standards IPC-A-610 Class 2, unless otherwise specified." AssemblyNote -10,5210 r0 top
? "Comment" MISTRAL_LOGO_25 6539.32,1005.04 r0 top
? "Comment" MHNP_M3_PANHEAD_PHILLIPS#1 3023.18,0 r0 top
? "Comment" MHNP_M3_PANHEAD_PHILLIPS#2 7404.17,0 r0 top
? "Comment" MHNP_M3_PANHEAD_PHILLIPS#2 7404.17,2000 r0 top locked
? "Comment" MHNP_M3_PANHEAD_PHILLIPS#1 3023.18,2000 r0 top locked
? "Comment" MHNP_M3_PANHEAD_PHILLIPS#2 4.17,2000 r0 top
? "Comment" MHNP_M3_PANHEAD_PHILLIPS#2 4.17,0 r0 top locked

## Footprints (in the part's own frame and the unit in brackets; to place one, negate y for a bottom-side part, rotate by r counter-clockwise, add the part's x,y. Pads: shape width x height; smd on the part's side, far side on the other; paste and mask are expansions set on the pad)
0201 [mm] "Data from Kemet datasheet CC101_COM dated 7/28/11"
  rect 0.46x0.42 smd mask+0.048: 1(-0.33,0) 2(0.33,0)
  body extent -0.31,-0.16 0.31,0.16, height 0.26
0402 [mm] "0402 from SM-752 data"
  rect 0.8x0.6 smd: 1(-0.6,0) 2(0.6,0)
  silkscreen extent -1.22,-0.52 1.22,0.52, body extent -0.55,-0.3 0.55,0.3, height 0.6
0402_070 [mil] "SMD, 2-Leads, Body 1.2x0.7mm, Height 0.7mm"
  rect 15x24 smd: 1(-20,0) 2(20,0)
  body extent -24,-14 24,14, height 28
0402L [mm] "0402 from SM-752 data"
  rect 0.6x0.5 smd: 1(-0.5,0) 2(0.5,0)
  body extent -0.55,-0.3 0.55,0.3, height 0.6
0402S [mil] "Based on C0402S footprint from PADS legacy"
  rect 15x24 smd: 1(-20,0) 2(20,0)
  body extent -22,-12 22,12, height 24
0603 [mm] "0603 from SM-752 data"
  rect 1x0.95 smd: 1(-0.8,0) 2(0.8,0)
  silkscreen extent -1.52,-0.69 1.52,0.69, body extent -0.87,-0.47 0.87,0.47, height 1
0805_HV [mil] "0805 with 30mil clearance between pads"
  rect 50x63 smd: 1(-40,0) 2(40,0)
  silkscreen extent -74,-40 74,40, body extent -43,-29 43,29, height 57
1210_270 [mm] "1210"
  rect 1.3x2.7 smd: 1(-1.45,0) 2(1.45,0)
  silkscreen extent -2.32,-1.57 2.32,1.57, body extent -1.7,-1.35 1.7,1.35, height 2.7
1808 [mm] "Chip Capacitor, Body 4.6x2.0mm, IPC Medium Density"
  rect 1.4x2.3 smd: 1(-2.1,0) 2(2.1,0)
  silkscreen extent -3.1,-1.45 3.1,1.45, body extent -2.47,-1.2 2.47,1.2, height 2.03
Abracon_ABM10W [mm] "SMD, 4-Leads, Body 2x2.5mm"
  rrect12% 0.85x1.2 smd: 1(-0.6,0.813) 2(-0.6,-0.813) 3(0.6,-0.813) 4(0.6,0.813)
  body extent -1.05,-1.3 1.05,1.3, height 0.6
AssemblyNote [mil] "Assembly Note"
AssemblyNoteLabel [mil] "Assembly Note for PCB Labels"
BOOSTERPACK_40PIN_J1J3 [mm] "Receptacle, 2.54mm, 10x2, TH"
  rrect6% 1.55x1.55 hole 1.02: 1(1.27,11.43)
  round 1.55 hole 1.02: 2(1.27,8.89) 3(1.27,6.35) 4(1.27,3.81) 5(1.27,1.27) 6(1.27,-1.27) 7(1.27,-3.81) 8(1.27,-6.35) 9(1.27,-8.89) 10(1.27,-11.43) 21(-1.27,11.43) 22(-1.27,8.89) 23(-1.27,6.35) 24(-1.27,3.81) 25(-1.27,1.27) 26(-1.27,-1.27) 27(-1.27,-3.81) 28(-1.27,-6.35) 29(-1.27,-8.89) 30(-1.27,-11.43)
  silkscreen extent -2.48,-12.95 2.48,12.95, body extent -2.48,-12.95 2.48,12.95, height 8.51
BoosterPack_40pin_J2J4 [mm] "Receptacle, 2.54mm, 10x2, TH"
  round 1.55 hole 1.02: 11(-1.27,-11.43) 12(-1.27,-8.89) 13(-1.27,-6.35) 14(-1.27,-3.81) 15(-1.27,-1.27) 16(-1.27,1.27) 17(-1.27,3.81) 18(-1.27,6.35) 19(-1.27,8.89) 20(-1.27,11.43) 31(1.27,-11.43) 32(1.27,-8.89) 33(1.27,-6.35) 34(1.27,-3.81) 35(1.27,-1.27) 36(1.27,1.27) 37(1.27,3.81) 38(1.27,6.35) 39(1.27,8.89) 40(1.27,11.43)
  silkscreen extent -7.62,-12.95 2.48,12.95, body extent -2.48,-12.95 2.48,12.95, height 8.51
BOOSTERPACK_40PIN_J5J7 [mm] "Receptacle, 2.54mm, 10x2, TH"
  round 1.55 hole 1.02: 41(1.27,11.43) 42(1.27,8.89) 43(1.27,6.35) 44(1.27,3.81) 45(1.27,1.27) 46(1.27,-1.27) 47(1.27,-3.81) 48(1.27,-6.35) 49(1.27,-8.89) 50(1.27,-11.43) 61(-1.27,11.43) 62(-1.27,8.89) 63(-1.27,6.35) 64(-1.27,3.81) 65(-1.27,1.27) 66(-1.27,-1.27) 67(-1.27,-3.81) 68(-1.27,-6.35) 69(-1.27,-8.89) 70(-1.27,-11.43)
  silkscreen extent -2.48,-12.95 2.48,12.95, body extent -2.48,-12.95 2.48,12.95, height 8.51
BoosterPack_40pin_J6J8 [mm] "Receptacle, 2.54mm, 10x2, TH"
  round 1.55 hole 1.02: 51(-1.27,-11.43) 52(-1.27,-8.89) 53(-1.27,-6.35) 54(-1.27,-3.81) 55(-1.27,-1.27) 56(-1.27,1.27) 57(-1.27,3.81) 58(-1.27,6.35) 59(-1.27,8.89) 60(-1.27,11.43) 71(1.27,-11.43) 72(1.27,-8.89) 73(1.27,-6.35) 74(1.27,-3.81) 75(1.27,-1.27) 76(1.27,1.27) 77(1.27,3.81) 78(1.27,6.35) 79(1.27,8.89) 80(1.27,11.43)
  silkscreen extent -7.62,-12.95 2.48,12.95, body extent -2.48,-12.95 2.48,12.95, height 8.51
BRAKE_WAY_HOLES1X3 [mil]
  round 27 hole 32 unplated mask+5.5: ""(-50,49.37) ""(0,49.37) ""(50,49.37)
CE_Mark_5mm [mil] "Minimum text height for CE Mark"
  silkscreen extent -138,-98 138,98
D0008B_HV [mm] "SOIC, 8-Leads, Body 4.9x3.9mm, Pitch 1.27mm, HV / Isolation option"
  rrect17% 1.4x0.6 smd: 1(-2.75,1.905) 2(-2.75,0.635) 3(-2.75,-0.635) 4(-2.75,-1.905) 5(2.75,-1.905) 6(2.75,-0.635) 7(2.75,0.635) 8(2.75,1.905)
  silkscreen extent -3.3,-2.5 0.9,2.5, body extent -3,-2.45 3,2.45, height 1.63
D0008B_N [mil] "SOIC, 8-Leads, Body 4.9x3.9mm, Pitch 1.27mm, IPC Medium Density"
  oval 55x23.62 smd: 1(-108.5,75) 2(-108.5,25) 3(-108.5,-25) 4(-108.5,-75) 5(108.5,-75) 6(108.5,-25) 7(108.5,25) 8(108.5,75)
  silkscreen extent -130,-98 35,98, body extent -118,-96 118,96, height 64
D0016A_N [mm] "SOIC, 16-Leads, Body 9.9x3.9mm, Pitch 1.27mm, IPC Medium Density"
  oval 1.45x0.6 smd: 1(-2.725,4.445) 2(-2.725,3.175) 3(-2.725,1.905) 4(-2.725,0.635) 5(-2.725,-0.635) 6(-2.725,-1.905) 7(-2.725,-3.175) 8(-2.725,-4.445) 9(2.725,-4.445) 10(2.725,-3.175) 11(2.725,-1.905) 12(2.725,-0.635) 13(2.725,0.635) 14(2.725,1.905) 15(2.725,3.175) 16(2.725,4.445)
  silkscreen extent -3.3,-5 0.9,5, body extent -3,-4.95 3,4.95, height 1.6
DBV0005A-MFG [mm]
  rrect17% 1.1x0.6 smd paste+0 mask+0: 1(-1.3,0.95) 2(-1.3,0) 3(-1.3,-0.95) 4(1.3,-0.95) 5(1.3,0.95)
  silkscreen extent -2.57,-1.53 0.87,1.53, body extent -1.95,-1.78 1.95,1.78, height 0.25
DBV0005A_N [mm] "SOT23, 5-Leads, Body 2.9x1.6mm, Pitch 0.95mm, Lead Span 2.8mm, IPC Medium Density"
  rrect17% 1x0.6 smd: 1(-1.375,0.95) 2(-1.375,0) 3(-1.375,-0.95) 4(1.375,-0.95) 5(1.375,0.95)
  silkscreen extent -0.25,-1.55 0.25,1.55, body extent -1.42,-1.46 1.42,1.46, height 1.09
DBV0006A_N [mm] "SOT23, 6-Leads, Body 2.9x1.6mm, Pitch 0.95mm, Lead Span 2.8mm, IPC Medium Density"
  rrect17% 1x0.6 smd: 1(-1.375,0.95) 2(-1.375,0) 3(-1.375,-0.95) 4(1.375,-0.95) 5(1.375,0) 6(1.375,0.95)
  silkscreen extent -1.68,-1.55 0.5,1.55, body extent -1.42,-1.46 1.42,1.46, height 1.12
DBZ0003A_N [mm] "SOT23, 3-Leads, Body 2.9x1.3mm, Pitch 0.95mm, Lead Span 2.4mm, IPC Medium Density"
  rrect17% 1x0.6 smd: 1(-1.2,0.95) 2(-1.2,-0.95) 3(1.2,0)
  silkscreen extent 0.2,-1.5 0.7,1.5, body extent -1.26,-1.46 1.26,1.46, height 0.98
DCK0005A_N [mm] "SOT353, 5-Leads, Body 2x1.3mm, Pitch 0.65mm, Lead Span 2.1mm, IPC Medium Density"
  rrect25% 0.85x0.4 smd: 1(-1.125,0.65) 2(-1.125,0) 3(-1.125,-0.65) 4(1.125,-0.65) 5(1.125,0.65)
  silkscreen extent -1.48,-1.02 0.55,1.1, body extent -1.14,-1 1.14,1, height 0.95
DGK0008A_N [mm] "TSOP, 8-Leads, Body 3x3mm, Pitch 0.65mm, IPC Medium Density"
  oval 1.35x0.45 smd: 1(-2.225,0.975) 2(-2.225,0.325) 3(-2.225,-0.325) 4(-2.225,-0.975) 5(2.225,-0.975) 6(2.225,-0.325) 7(2.225,0.325) 8(2.225,0.975)
  silkscreen extent -2.75,-1.55 0.95,1.55, body extent -2.45,-1.5 2.45,1.5, height 0.96
DGS0010A_N [mm] "TSSOP, 10-Leads, Body 3x3mm, Pitch 0.5mm, IPC Medium Density"
  oval 1.35x0.3 smd: 1(-2.225,1) 2(-2.225,0.5) 3(-2.225,0) 4(-2.225,-0.5) 5(-2.225,-1) 6(2.225,-1) 7(2.225,-0.5) 8(2.225,0) 9(2.225,0.5) 10(2.225,1)
  silkscreen extent -2.75,-1.55 0.9,1.55, body extent -2.45,-1.5 2.45,1.5, height 0.96
DPY0002A [mm] "X1SON-2"
  rrect57% 0.35x0.6 smd paste-0.5 mask-0.05: 1(-0.325,0) 2(0.325,0)
  rrect50% 0.3x0.5 on Top Paste: 1S(-0.35,0) 2S(0.35,0)
  silkscreen extent -0.85,-0.02 -0.8,0.02, body extent -0.5,-0.3 0.5,0.3, height 0.45
DQA0010A#1 [mm] "SON, 10-Leads, Body 1x2.5mm, Pitch 0.5mm, TI Recommended"
  rrect50% 0.565x0.2 smd: 1(-0.417,1) 2(-0.417,0.5) 4(-0.417,-0.5) 5(-0.417,-1) 6(0.417,-1) 7(0.417,-0.5) 9(0.417,0.5) 10(0.417,1)
  rrect28% 0.565x0.36 on Top Paste: 3(-0.417,0) 8(0.417,0)
  rrect25% 0.565x0.4 smd paste-0.2: 3(-0.417,0) 8(0.417,0)
  silkscreen extent -0.67,-1.45 0.55,1.45, body extent -0.55,-1.3 0.55,1.3, height 0.56
DQA0010A#2 [mm] "SON, 10-Leads, Body 1x2.5mm, Pitch 0.5mm, TI Recommended"
  rrect50% 0.565x0.2 smd: 1(-0.417,1) 2(-0.417,0.5) 4(-0.417,-0.5) 5(-0.417,-1) 6(0.417,-1) 7(0.417,-0.5) 9(0.417,0.5) 10(0.417,1)
  rrect28% 0.565x0.36 on Bottom Paste: 3(-0.417,0) 8(0.417,0)
  rrect25% 0.565x0.4 smd paste-0.2: 3(-0.417,0) 8(0.417,0)
  silkscreen extent -0.67,-1.45 0.55,1.45, body extent -0.55,-1.3 0.55,1.3, height 0.56
DQC0010A [mm] "SON, 10-Leads, Body 2x3mm, Pitch 0.5mm, Thermal Pad 2.4x0.84mm"
  rrect40% 0.5x0.25 smd: 1(-0.95,1) 2(-0.95,0.5) 3(-0.95,0) 4(-0.95,-0.5) 5(-0.95,-1) 6(0.95,-1) 7(0.95,-0.5) 8(0.95,0) 9(0.95,0.5) 10(0.95,1)
  rrect12% 0.8x1.08 on Top Paste: 11(0,-0.64) 11(0,0.64)
  rrect12% 0.84x2.4 smd paste-0.42: 11(0,0)
  silkscreen extent -1.18,-1.68 1.17,1.68, body extent -1,-1.5 1,1.5, height 0.77
DRB0008B [mm] "SON, 8-Leads, Body 3x3mm, Pitch 0.65mm, Thermal Pad 2.4x1.65mm, TI Recommended"
  rrect33% 0.6x0.3 smd: 1(-1.4,0.975) 2(-1.4,0.325) 3(-1.4,-0.325) 4(-1.4,-0.975) 5(1.4,-0.975) 6(1.4,-0.325) 7(1.4,0.325) 8(1.4,0.975)
  rrect50% 1.47x1.06 on Top Paste: 9(0,0.63) 9(0,-0.63)
  rrect6% 1.65x2.4 smd paste-1.2: 9(0,0)
  silkscreen extent -1.73,-1.73 1.73,1.73, body extent -1.5,-1.5 1.5,1.5, height 0.96
DRB0008J [mm] "VSON-8"
  rrect33% 0.6x0.31 smd: 1(-1.4,0.975) 2(-1.4,0.325) 3(-1.4,-0.325) 4(-1.4,-0.975) 5(1.4,-0.975) 6(1.4,-0.325) 7(1.4,0.325) 8(1.4,0.975)
  rrect6% 1.65x2.4 smd paste-1.2: 9(0,0)
  silkscreen extent -1.73,-1.73 1.73,1.73, body extent -1.55,-1.55 1.55,1.55, height 1.01
DRC0010J [mm] "VSON-10"
  rrect42% 0.6x0.24 smd: 1(-1.4,1) 2(-1.4,0.5) 3(-1.4,0) 4(-1.4,-0.5) 5(-1.4,-1) 6(1.4,-1) 7(1.4,-0.5) 8(1.4,0) 9(1.4,0.5) 10(1.4,1)
  rrect12% 1.65x2.4 smd paste-1 mask-2: 11(0,0)
  Top Layer region: -0.375,-1.65 -0.375,-1.2 -0.775,-1.2 -0.794,-1.196 -0.81,-1.185 -0.821,-1.169 -0.825,-1.15 -0.825,-1.15 -0.825,1.15 -0.821,1.169 -0.81,1.185 -0.794,1.196 -0.775,1.2 -0.775,1.2 -0.375,1.2 -0.375,1.65 -0.371,1.669 -0.36,1.685 -0.344,1.696 -0.325,1.7 -0.325,1.7 -0.325,1.7 -0.175,1.7 -0.175,1.7 -0.156,1.696 -0.14,1.685 -0.129,1.669 -0.125,1.65 -0.125,1.65 -0.125,1.2 0.125,1.2 0.125,1.65 0.129,1.669 0.14,1.685 0.156,1.696 0.175,1.7 0.175,1.7 0.175,1.7 0.325,1.7 0.325,1.7 0.344,1.696 0.36,1.685 0.371,1.669 0.375,1.65 0.375,1.65 0.375,1.2 0.775,1.2 0.794,1.196 0.81,1.185 0.821,1.169 0.825,1.15 0.825,1.15 0.825,-1.15 0.821,-1.169 0.81,-1.185 0.794,-1.196 0.775,-1.2 0.775,-1.2 0.375,-1.2 0.375,-1.65 0.371,-1.669 0.36,-1.685 0.344,-1.696 0.325,-1.7 0.325,-1.7 0.175,-1.7 0.156,-1.696 0.14,-1.685 0.129,-1.669 0.125,-1.65 0.125,-1.65 0.125,-1.2 -0.125,-1.2 -0.125,-1.65 -0.129,-1.669 -0.14,-1.685 -0.156,-1.696 -0.175,-1.7 -0.175,-1.7 -0.325,-1.7 -0.344,-1.696 -0.36,-1.685 -0.371,-1.669 -0.375,-1.65
  body extent -1.5,-1.5 1.5,1.5, height 1
DRL0005A [mm] "SOTFL, 5-Flat Leads, Body 1.2x1.6x0.6mm, Pitch 0.5mm, TI recommended"
  rrect33% 0.67x0.3 smd: 1(-0.74,0.5) 2(-0.74,0) 3(-0.74,-0.5) 4(0.74,-0.5) 5(0.74,0.5)
  silkscreen extent -0.9,-0.95 0.5,0.95, body extent -0.85,-0.85 0.85,0.85, height 0.62
DSF0006A [mm] "TI recommended land pattern"
  rrect59% 0.6x0.17 smd mask+0.045: 1(-0.4,0.35) 2(-0.4,0) 3(-0.4,-0.35) 4(0.4,-0.35) 5(0.4,0) 6(0.4,0.35)
  silkscreen extent -0.6,-0.63 0.6,0.63, body extent -0.5,-0.5 0.5,0.5, height 0.48
DSG0008B [mm] "SON, 8-Leads, Body 2x2mm, Pitch 0.5mm, Thermal Pad 1.6x0.9mm, TI Recommended"
  rrect14% 0.9x0.7 on Top Paste: 0(0,-0.45) 0(0,0.45)
  rrect40% 0.5x0.25 smd: 1(-0.95,0.75) 2(-0.95,0.25) 3(-0.95,-0.25) 4(-0.95,-0.75) 5(0.95,-0.75) 6(0.95,-0.25) 7(0.95,0.25) 8(0.95,0.75)
  rrect11% 0.9x1.6 smd paste-0.45: 9(0,0)
  silkscreen extent -1.07,-1.15 1.07,1.15, body extent -1,-1 1,1, height 0.77
FCC_disclaimer [mil]
Fiducial10-20 [mm]
  round 1 smd mask+0.5: 1(0,0)
  Top Layer keep-out circle w1.178: c0,0 r0.5
FP-2012670005_CONN_USB_9MM39_8MM21-MFG [mm]
  rrect100% 1.1x2.1 hole 1.6 slot 0.6 at 0 deg paste-2539.97 mask+0: 1(-4.32,3.205) 2(4.32,3.205)
  rrect100% 1.1x3.6 smd paste-1000 mask+0: 3(-4.62,-1.655) 4(4.62,-1.655)
  rrect100% 1.1x3.6 smd far side paste-1000 mask+0: 3(-4.62,-1.655) 4(4.62,-1.655)
  rrect100% 0.6x2.1 hole 2.1 slot 0.6 at 0 deg paste-2539.97 mask+0: 3(-4.62,-2.155) 4(4.62,-2.155)
  rrect33% 0.3x0.7 smd paste+0 mask+0: A1(-3,4.015) A2(-2.5,4.015) A3(-2,4.015) A4(-1.5,4.015) A5(-1,4.015) A6(-0.5,4.015) A7(0.5,4.015) A8(1,4.015) A9(1.5,4.015) A10(2,4.015) A11(2.5,4.015) A12(3,4.015) B2(2.25,2.315) B3(1.75,2.315) B4(1.25,2.315) B5(0.75,2.315) B6(0.25,2.315) B7(-0.25,2.315) B8(-0.75,2.315) B9(-1.25,2.315) B10(-1.75,2.315) B11(-2.25,2.315)
  rrect14% 0.9x0.7 smd paste+0 mask+0: B1(3.05,2.315) B12(-3.05,2.315)
  silkscreen extent -4.77,0.52 4.77,5.04, body extent -5.27,-4.33 5.27,4.46, height 0.25
FP-74405020100_SMT_IND_2MM0_1MM6-MFG [mm]
  rect 0.8x1.7 smd paste+0 mask+0: 1(-0.8,0) 2(0.8,0)
  body extent -1.3,-1 1.3,1, height 0.25
FP-416131160804_SMT_SW-MFG [mm]
  rrect13% 0.76x1.27 smd paste+0 mask+0: 1(-1.905,-3.81) 2(-0.635,-3.81) 3(0.635,-3.81) 4(1.905,-3.81) 5(1.905,3.81) 6(0.635,3.81) 7(-0.635,3.81) 8(-1.905,3.81)
  silkscreen extent -3.27,-4.12 3.27,2.93, body extent -3.37,-4.54 3.37,4.54, height 0.25
FP-434351045816_SMT_SW_4MM7_4MM5-MFG [mm]
  rrect10% 1.2x1 smd paste+0 mask+0: 1(2.8,0.85) 2(2.8,-0.85) 3(-2.8,0.85) 4(-2.8,-0.85)
  silkscreen extent -2.4,0.73 4.07,1.85, body extent -3.5,-2.95 3.5,1.95, height 0.25
FP-BLM18EG121SN1D_0603-MFG [mm]
  rrect15% 0.65x0.7 smd paste+0 mask+0: 1(-0.675,0) 2(0.675,0)
  silkscreen extent -0.87,-0.8 0.87,0.8, body extent -0.8,-0.4 0.8,0.4, height 0.95
FP-FH12A-40S-0.5SH(55)_FFC40-MFG [mm]
  rrect33% 0.3x1.3 smd paste-1000 mask+0: 1(9.75,-3.725) 2(9.25,-3.725) 3(8.75,-3.725) 4(8.25,-3.725) 5(7.75,-3.725) 6(7.25,-3.725) 7(6.75,-3.725) 8(6.25,-3.725) 9(5.75,-3.725) 10(5.25,-3.725) 11(4.75,-3.725) 12(4.25,-3.725) 13(3.75,-3.725) 14(3.25,-3.725) 15(2.75,-3.725) 16(2.25,-3.725) 17(1.75,-3.725) 18(1.25,-3.725) 19(0.75,-3.725) 20(0.25,-3.725) 21(-0.25,-3.725) 22(-0.75,-3.725) 23(-1.25,-3.725) 24(-1.75,-3.725) 25(-2.25,-3.725) 26(-2.75,-3.725) 27(-3.25,-3.725) 28(-3.75,-3.725) 29(-4.25,-3.725) 30(-4.75,-3.725) 31(-5.25,-3.725) 32(-5.75,-3.725) 33(-6.25,-3.725) 34(-6.75,-3.725) 35(-7.25,-3.725) 36(-7.75,-3.725) 37(-8.25,-3.725) 38(-8.75,-3.725) 39(-9.25,-3.725) 40(-9.75,-3.725)
  rrect6% 1.8x2.2 smd paste+0 mask+0: 41(-11.65,-0.475) 42(11.65,-0.475)
  silkscreen extent -12.35,-5.07 12.35,3.2, body extent -12.25,-3.82 12.25,2.95, height 3.5
FP-GRM033C80J105ME05D_0201-MFG [mm]
  rrect33% 0.3x0.35 smd paste+0 mask+0: 1(-0.282,0) 2(0.282,0)
  silkscreen extent -0.35,-0.58 0.35,0.58, body extent -0.3,-0.15 0.3,0.15, height 0.39
FP-LPJG16314A4NL_CONN_RJ45-MFG [mm]
  rrect7% 1.4x1.4 hole 0.9 paste-2539.97 mask+0: 1(-5.715,9.015)
  round 1.4 hole 0.9 paste-2539.97 mask+0: 2(-4.445,6.475) 3(-3.175,9.015) 4(-1.905,6.475) 5(-0.635,9.015) 6(0.635,6.475) 7(1.905,9.015) 8(3.175,6.475) 9(4.445,9.015) 10(5.715,6.475)
  round 1.57 hole 1.02 paste-2539.97 mask+0: 11(6.725,-2.415) 12(6.725,-4.445) 13(-6.725,-2.415) 14(-6.725,-4.445)
  round 2.6 hole 1.7 paste-2539.97 mask+0: 15(-7.875,3.175) 16(7.875,3.175)
  round 3.25 hole 3.25 unplated paste-2539.97 mask+0: ""(-5.715,0.125) ""(5.715,0.125)
  silkscreen extent -9.65,-10.75 8.1,10.75, body extent -9.28,-10.85 9.28,10.85, height 0.25
FP-S25FL128SAGNFI000_WSON8-IPC_B [mm]
  rrect25% 0.961x0.392 smd paste+0 mask+0: 1(-3.876,1.905)
  rrect100% 0.961x0.392 smd paste+0 mask+0: 2(-3.876,0.635) 3(-3.876,-0.635) 4(-3.876,-1.905) 5(3.876,-1.905) 6(3.876,-0.635) 7(3.876,0.635) 8(3.876,1.905)
  rrect2% 4.9x4.75 smd paste-1000 mask+0: 9(0,0)
  silkscreen extent -5.03,-3 4,3, body extent -4.61,-3.25 4.61,3.25, height 0.25
Hirose_DM3BT-DSF-PEJS [mm] "Conncetor, micro SD, 8+2 Pos, R/A, SMT"
  rrect14% 0.7x1.4 smd: 1(-3.2,7.8) 2(-2.1,7.8) 3(-1,7.8) 4(0.1,7.8) 5(1.2,7.8) 6(2.3,7.8) 7(3.4,7.8) 8(4.5,7.8)
  rrect8% 1.2x0.8 smd: 9(6.3,-2.6)
  rrect14% 0.7x1.2 smd: 10(5.45,7.9)
  rrect10% 1x1.4 smd: S1(-5.1,7.8)
  rrect8% 1.2x1.2 smd: S2(6.3,3.6)
  rrect8% 1.2x3.2 smd: S3(6.3,-6.2)
  rrect8% 1x1 smd: S4(-7,-7)
  Top Layer region: -7.75,-8.15 -5.75,-8.15 -5.75,-7.65 -6.1,-7.65 -6.25,-7.5 -6.25,-6.25 -7.75,-6.25
  body extent -6.93,-7.98 6.93,7.98, height 2.38
Label_650x200 [mil] "Thermal Transfer Label"
  round 1 on Mech13: 0(0,0)
  silkscreen extent -325,-100 325,100, body extent -325,-100 325,100, height 1
MHNP_M3_PANHEAD_PHILLIPS#1 [mil]
  round 121 hole 126 unplated mask+5.5: ""(0,0)
  Keep-Out Layer circle w1: c0,0 r126
MHNP_M3_PANHEAD_PHILLIPS#2 [mil]
  round 121 hole 126 unplated mask+5.5: ""(-4.17,0)
  Keep-Out Layer circle w1: c0,0 r126
MISTRAL_LOGO_25 [mil]
  silkscreen extent 0,0 297,162
Molex_1051640001 [mm] "Receptacle, USB 2.0, Micro B, 5 Pos, 0.65mm Pitch, R/A, SMT"
  rrect22% 0.45x1.38 smd: 1(1.3,4.11) 2(0.65,4.11) 3(0,4.11) 4(-0.65,4.11) 5(-1.3,4.11)
  rrect7% 1.475x2.1 smd: 6(-2.462,3.75) 11(2.462,3.75)
  rrect100% 1.4x2.1 hole 0.6 slot 1.3 at 90 deg: 7(-3.95,1.45) 10(3.95,1.45)
  rrect7% 1.375x1.9 smd: 8(-0.937,1.45) 9(0.937,1.45)
  silkscreen extent 1.2,5.1 1.4,5.4, body extent -4.1,-0.7 4.1,4.47, height 2.45
NDK_NX3225GA [mm] "NDK"
  rect 1.2x1.4 smd: 1(-0.8,1.1) 2(-0.8,-1.1) 3(0.8,-1.1) 4(0.8,1.1)
  silkscreen extent -1.9,-0.1 1.4,2, body extent -1.3,-1.65 1.3,1.65, height 0.9
On-Shore_OSTTE030161 [mm] "Terminal Block, 3.5mm, 3x1, TH"
  rrect50% 1.7x1.7 hole 1.2: 1(-3.5,0)
  round 1.7 hole 1.2: 2(0,0) 3(3.5,0)
  silkscreen extent -5.25,-3.6 5.25,4.05, body extent -5.75,-3.6 5.75,3.4, height 8.4
PBC03SAAN [mm] "Sullins 100mil, 1x3, 230 mil above insulator"
  rect 1.65x1.65 hole 1.016: 1(-2.54,0)
  round 1.65 hole 1.016: 2(0,0) 3(2.54,0)
  silkscreen extent -3.81,-1.27 3.81,1.27, body extent -3.81,-1.27 3.81,1.27, height 8.38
